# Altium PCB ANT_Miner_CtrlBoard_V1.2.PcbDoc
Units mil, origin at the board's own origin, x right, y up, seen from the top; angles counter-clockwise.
Board outline 5078.74 x 1377.95 mil, 2 copper layers (Top Layer, Bottom Layer); 116 components, 89 nets, 414 pads, 100 vias.
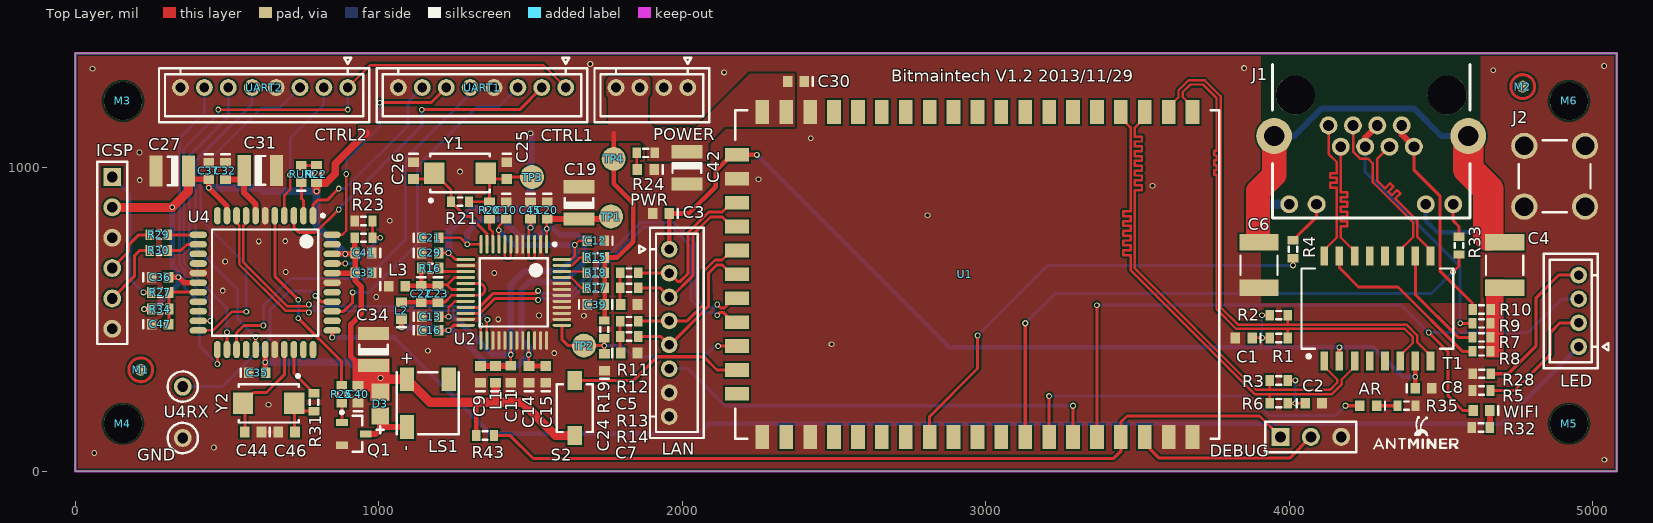
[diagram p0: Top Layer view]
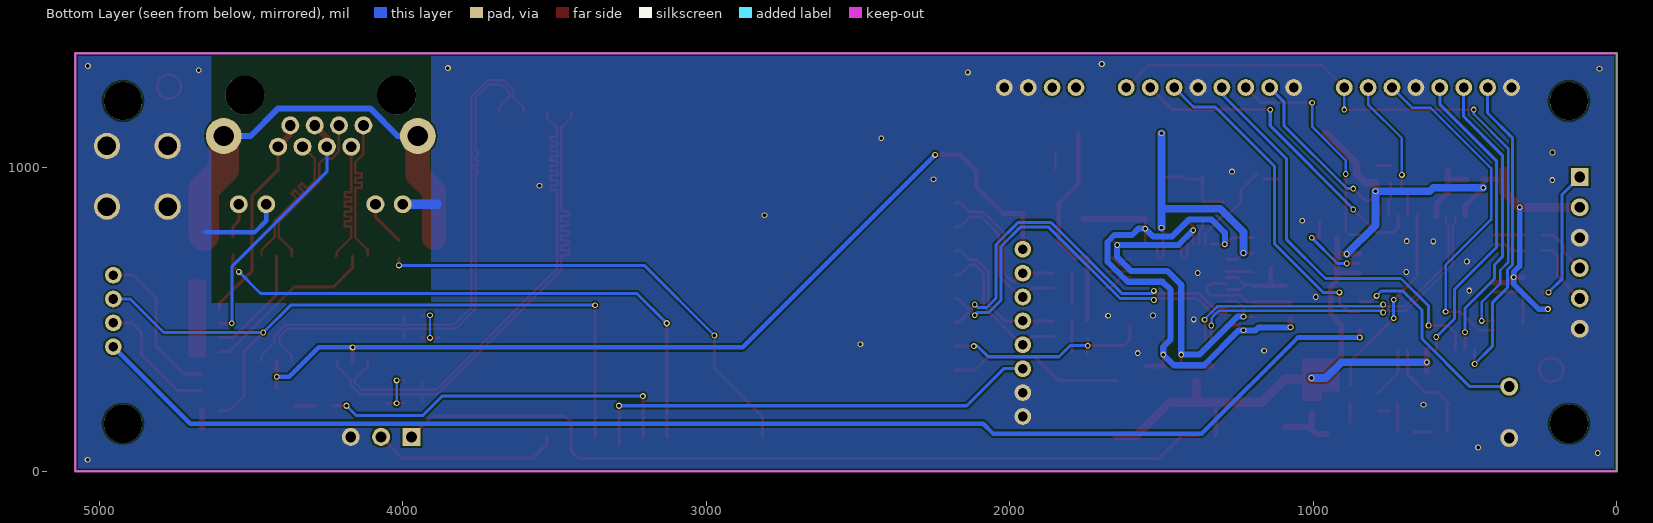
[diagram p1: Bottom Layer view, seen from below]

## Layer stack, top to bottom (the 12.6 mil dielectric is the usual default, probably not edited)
Top Layer: signal copper 1.4
Dielectric: core 12.6, FR-4, Dk 4.8
Bottom Layer: signal copper 1.4

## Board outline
5078.74,1377.95 5078.74,0 0,0 0,1377.95

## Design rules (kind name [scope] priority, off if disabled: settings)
Clearance [All] p1: gap=6
DiffPairsRouting [All] p1: maxlimit=6 minlimit=6 mostfreqgap=6 maxuncoupledlength=500
HoleSize [All] p1: absolutevalues=TRUE maxlimit=200 minlimit=1 maxpercent=80.000 minpercent=20.000
MinimumSolderMaskSliver [All] p1: minsoldermaskwidth=1
PolygonConnect [All] p1: connectstyle=Direct reliefconductorwidth=10 reliefentries=4 polygonreliefangle="90 Angle" airgapwidth=10
RoutingVias [All] p1: holewidth=12 width=20 viastyle="Through Hole" minholewidth=12 minwidth=20 maxholewidth=28 maxwidth=50
SilkToSilkClearance [All] p1: silktosilkclearance=1
SilkToSolderMaskClearance SilkscreenOverComponentPads [IsPad] p1: minsilkscreentomaskgap=1 clearancetoexposedcopper=TRUE
SolderMaskExpansion [All] p1: expansion=4
Width Width_VDD [InNet('VDD')] p1: maxlimit=100 minlimit=10 preferedwidth=10
Width Width_GND [InNet('GND')] p2: maxlimit=100 minlimit=8 preferedwidth=15
Width Width_PLL [InNet('VPLL')] p3: maxlimit=50 minlimit=10 preferedwidth=10
Width Width_VCC [InNet('VCC')] p4: maxlimit=50 minlimit=10 preferedwidth=10
Width [All] p5: maxlimit=100 minlimit=8 preferedwidth=8
23 further rules are at their usual default settings.

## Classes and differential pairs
differential pair D1: +D1_P -D1_N
differential pair LAN1_RX: +LAN1_RX_P -LAN1_RX_N
differential pair LAN1_TX: +LAN1_TX_P -LAN1_TX_N
differential pair USB: +USB_P -USB_N
differential pair WAN_RX: +WAN_RX_P -WAN_RX_N
differential pair WAN_TX: +WAN_TX_P -WAN_TX_N
differential pair WANRX: +WANRX_P -WANRX_N
differential pair WANTX: +WANTX_P -WANTX_N

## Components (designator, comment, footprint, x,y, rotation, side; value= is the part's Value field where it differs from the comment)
AR "Green" LED0603(1608) 4259.84,216.54 r180 top
C1 "100nF" CC0603(1608) 3849.92,439.92 r180 top
C2 "100nF" CC0603(1608) 4079.92,224.92 r0 top
C3 "100nF" CC0603(1608) 1929.92,849.92 r180 top
C4 "10nF/2KV" 1812 4708.92,679.92 r270 top
C5 "100nF" CC0603(1608) 1824.92,549.92 r0 top
C6 "10nF/2KV" 1812 3899.92,679.92 r270 top
C7 "100nF" CC0603(1608) 1824.92,389.92 r0 top
C8 "100nF" CC0603(1608) 4441.92,273.92 r0 top
C9 "4.7uF" CC0603(1608) 1334.92,319.92 r90 top
C10 "100nF" CC0603(1608) 1419.92,859.92 r270 top
C11 "100nF" CC0603(1608) 1435.08,320.08 r90 top
C12 "100nF" CC0603(1608) 1714.92,759.92 r180 top
C13 "100nF" CC0603(1608) 1169.92,509.92 r0 top
C14 "4.7uF" CC0603(1608) 1494.92,319.92 r90 top
C15 "100nF" CC0603(1608) 1549.92,319.92 r90 top
C16 "100nF" CC0603(1608) 1169.92,464.92 r0 top
C19 "22uF/10V" CC1210(3225) 1659.92,884.92 r270 top
C20 "4.7uF" CC0603(1608) 1554.92,859.92 r270 top
C21 "100nF" CC0603(1608) 1169.92,769.92 r0 top
C22 "100nF" CC0603(1608) 1139.92,584.92 r270 top
C23 "100nF" CC0603(1608) 1194.92,584.92 r270 top
C24 "4.7uF" CC0603(1608) 1743.92,359.92 r90 top
C25 "22pF" CC0603(1608) 1421.34,990.98 r270 top
C26 "22pF" CC0603(1608) 1114.25,990.98 r270 top
C27 "22uF/10V" CC1210(3225) 319.92,989.92 r0 top
C29 "100nF" CC0603(1608) 1169.92,719.92 r0 top
C30 "100nF" CC0603(1608) 2374.92,1284.92 r180 top
C31 "10uF/10V" CC1210(3225) 609.88,991.93 r180 top
C32 "100nF" CC0603(1608) 494.92,989.92 r270 top
C33 "100nF" CC0603(1608) 949.92,654.92 r180 top
C34 "22uF/10V" CC1210(3225) 982.92,401.92 r270 top
C35 "100nF" CC0603(1608) 599.92,324.92 r0 top
C36 "100nF" CC0603(1608) 279.92,639.92 r0 top
C37 "100nF" CC0603(1608) 439.92,989.92 r270 top
C39 "100nF" CC0603(1608) 1714.92,549.92 r0 top
C40 "100nF" CC0603(1608) 931.92,253.92 r90 top
C41 "100nF" CC0603(1608) 949.92,719.92 r180 top
C42 "22uF/6.3V" CC1210(3225) 2014.92,999.92 r90 top
C44 "22pF" CC0603(1608) 586.26,129.72 r180 top
C45 "100nF" CC0603(1608) 1499.92,859.92 r270 top
C46 "22pF" CC0603(1608) 696.5,129.72 r0 top
C47 "100nF" CC0603(1608) 279.92,484.92 r0 top
D3 "1N4148" DIODE0805 1004.92,182.92 r180 top
DEBUG "HDR1X3" HDR1X3 3970.92,113.92 r0 top
GND "GND" TP_DIP_1.5mm 354.33,110.24 r0 top
ICSP "HDR1X6" HDR1X6 122.05,970.08 r270 top
J1 "WAN" RJ45_2LED_DIP 4269.69,1240.16 r180 top locked
J2 "SMA HOLE" SMA_HOLE 4874.02,972.44 r0 top
L1 "600/100M" INDC1608L 1384.92,319.92 r90 top
L2 "600/100M" INDC1608L 1074.92,529.92 r90 top
L3 "600/100M" INDC1608L 1059.92,609.92 r0 top
LAN "Header 8" 8PIN_180 1956.69,456.69 r270 top locked
LED "Header 4" 4PIN_180 4952.92,528.81 r90 top
LS1 "Bell" YR5025A 1161.92,224.92 r270 top
M1 "MASK" MASK 215.92,334.92 r0 top
M2 "MASK" MASK 4768.92,1267.92 r0 top
M3 "Mount Hole" HOLE_3.2#1 157.48,1220.47 r0 top locked
M4 "Mount Hole" HOLE_3.2#1 157.48,157.48 r0 top locked
M5 "Mount Hole" HOLE_3.2#2 4763.78,157.48 r0 top locked
M6 "Mount Hole" HOLE_3.2#2 4763.78,1220.47 r0 top locked
POWER "Header 4" 4PIN_180 1899.81,1264.92 r180 top locked
PWR "Red" LED0603(1608) 1879.92,994.92 r180 top
Q1 "MMBT3904" SOT23_L 917.92,123.92 r0 top
R1 "49.9ohm/1%" RR0603(1608) 3964.92,439.92 r0 top
R2 "49.9ohm/1%" RR0603(1608) 3964.92,514.92 r0 top
R3 "49.9ohm/1%" RR0603(1608) 3964.92,299.92 r180 top
R4 "270" RR0603(1608) 4011.92,731.92 r90 top
R5 "NC" RR0603(1608) 4632.92,266.92 r180 top
R6 "49.9ohm/1%" RR0603(1608) 3964.92,224.92 r180 top
R7 "75ohm/1%" RR0603(1608) 4632.92,441.92 r0 top
R8 "75ohm/1%" RR0603(1608) 4632.92,395.92 r0 top
R9 "75ohm/1%" RR0603(1608) 4632.92,487.92 r0 top
R10 "75ohm/1%" RR0603(1608) 4633.39,533.92 r0 top
R11 "49.9ohm/1%" RR0603(1608) 1824.92,654.92 r0 top
R12 "49.9ohm/1%" RR0603(1608) 1824.92,604.92 r0 top
R13 "49.9ohm/1%" RR0603(1608) 1824.92,494.92 r0 top
R14 "49.9ohm/1%" RR0603(1608) 1824.92,444.92 r0 top
R15 "10K" RR0603(1608) 1714.92,704.92 r180 top
R16 "2.43K/1%" RR0603(1608) 1169.92,669.92 r0 top
R17 "510" RR0603(1608) 1714.92,604.92 r0 top
R18 "10K" RR0603(1608) 1714.92,654.92 r0 top
R19 "10K" RR0603(1608) 1742.92,467.92 r90 top
R20 "0" RR0603(1608) 1364.92,859.92 r90 top
R21 "1M" RR0603(1608) 1267.8,888.62 r0 top
R22 "1K" RR0603(1608) 794.92,979.92 r270 top
R23 "0" RR0603(1608) 949.92,769.92 r180 top
R24 "1K" RR0603(1608) 1879.92,1049.92 r0 top
R25 "1K" RR0603(1608) 877.92,253.92 r90 top
R26 "NC" RR0603(1608) 949.92,824.92 r0 top
R27 "10" RR0603(1608) 279.92,589.92 r180 top
R28 "NC" RR0603(1608) 4633.92,321.92 r180 top
R29 "10" RR0603(1608) 275.59,779.53 r180 top
R30 "10" RR0603(1608) 275.59,728.35 r180 top
R31 "0" RR0603(1608) 787.05,228.15 r90 top
R32 "1K" RR0603(1608) 4630.95,144.89 r0 top
R33 "270" RR0603(1608) 4559.06,744.09 r90 top
R34 "4.7K" RR0603(1608) 279.92,534.92 r180 top
R35 "1K" RR0603(1608) 4385.83,216.54 r180 top
R43 "4.7K" RR0603(1608) 1350.39,118.11 r180 top
RUN "Green" LED0603(1608) 744.92,979.92 r90 top
S2 "SW-PB" SWITCH_3x4 1645.67,208.66 r0 top
T1 "PM44-11BP" PM44-11BP 4289.92,536.69 r0 top locked
TP1 "TP" TP2 1764.92,839.92 r180 top
TP2 "TP" TP2 1675.92,414.44 r180 top
TP3 "TP" TP2 1504.92,969.92 r270 top
TP4 "TP" TP2 1773.92,1029.92 r0 top
U1 "AR9331_49PIN" AR9331_49PIN 2263.78,107.95 r0 top locked
U2 "μPD720114" TQFP48_L 1444.92,589.92 r270 top locked
U4 "PIC32MX250F128D" TQFP44_L 625.98,622.05 r270 top locked
U4RX "RX" TP_DIP_1.5mm 354.33,279.53 r0 top
UART1 "CTRL1" 8PIN_180 1340.33,1264.92 r180 top locked
UART2 "CTRL2" 8PIN_180 622.51,1264.92 r180 top locked
WIFI "Green" LED0603(1608) 4632.92,200.92 r180 top
Y1 "30MHz" 4SMX 1267.8,983.11 r0 top
Y2 "8M" 4SMX 637.44,224.21 r180 top

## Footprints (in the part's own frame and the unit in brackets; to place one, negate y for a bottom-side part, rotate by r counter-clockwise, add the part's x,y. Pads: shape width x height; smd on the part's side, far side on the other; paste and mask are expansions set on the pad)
4PIN_180 [mm]
  round 1.4 hole 0.8: 1(-3,0) 2(-1,0) 3(1,0) 4(3,0)
  silkscreen extent -4.8,-2.5 4.8,2.9, body extent -5,-1.8 5,3, height 6.1
4SMX [mm]
  rect 1.7x1.8 smd: 1(-2.15,0) 2(2.15,0)
  silkscreen extent -2.57,-2.42 2.5,1.6
8PIN_180 [mm]
  round 1.4 hole 0.8: 1(-7,0) 2(-5,0) 3(-3,0) 4(-1,0) 5(1,0) 6(3,0) 7(5,0) 8(7,0)
  silkscreen extent -8.8,-2.5 8.8,2.9, body extent -9,-1.8 9,3, height 6.1
1812 [mm] "Chip Capacitor, Body 4.5x3.2mm, IPC High Density"
  rect 1.4x3.3 smd: 1(-1.9,0) 2(1.9,0)
  silkscreen extent -0.8,-1.55 0.8,1.55, body extent -2.4,-1.7 2.4,1.7, height 1.4
AR9331_49PIN [mm] "AR9331 49PIN"
  rect 1.143x2 smd: 1(0,0.158) 2(2,0.158) 3(4,0.158) 4(6,0.158) 5(8,0.158) 6(10,0.158) 7(12,0.158) 8(14,0.158) 9(16,0.158) 10(18,0.158) 11(20,0.158) 12(22,0.158) 13(24,0.158) 14(26,0.158) 15(28,0.158) 16(30,0.158) 17(32,0.158) 18(34,0.158) 19(36,0.158) 20(36,27.341) 21(34,27.341) 22(32,27.341) 23(30,27.341) 24(28,27.341) 25(26,27.341) 26(24,27.341) 27(22,27.341) 28(20,27.341) 29(18,27.341) 30(16,27.341) 31(14,27.341) 32(12,27.341) 33(10,27.341) 34(8,27.341) 35(6,27.341) 36(4,27.341) 37(2,27.341) 38(0,27.341)
  rect 2x1.146 smd: 39(-2.11,23.75) 40(-2.11,21.75) 41(-2.11,19.75) 42(-2.11,17.75) 43(-2.11,15.75) 44(-2.11,13.75) 45(-2.11,11.75) 46(-2.11,9.75) 47(-2.11,7.75) 48(-2.11,5.75) 49(-2.11,3.75)
  silkscreen extent -2.25,0 38.25,27.5
CC0603(1608) [mm] "Chip Capacitor, Body 1.6x0.8mm, IPC High Density"
  rect 0.8x0.9 smd: 1(-0.7,0) 2(0.7,0)
  silkscreen extent -1.4,-0.35 -1.4,0.35, body extent -0.87,-0.48 0.87,0.47, height 0.85
CC1210(3225) [mm] "Chip Capacitor, Body 3.2x2.5mm, IPC High Density"
  rect 1.1x2.6 smd: 1(-1.35,0) 2(1.35,0)
  silkscreen extent -0.4,-1.2 0.42,1.2, body extent -1.7,-1.35 1.7,1.35, height 1.35
DIODE0805 [mm]
  rect 1.5x1.4 smd: 1(0,0) 2(0,-2)
  silkscreen extent -0.28,0.88 0.28,1.44, body extent -0.7,-2.07 0.7,0.07, height 0.7
HDR1X3 [mm] "Connector; Header; 3 Position"
  rect 1.5x1.5 hole 0.9: 1(0,0)
  round 1.5 hole 0.9: 2(2.54,0) 3(5.08,0)
  silkscreen extent -1.27,-1.27 6.35,1.27
HDR1X6 [mm] "Connector; Header; 6 Position"
  rect 1.5x1.5 hole 0.9: 1(0,0)
  round 1.5 hole 0.9: 2(2.54,0) 3(5.08,0) 4(7.62,0) 5(10.16,0) 6(12.7,0)
  silkscreen extent -1.27,-1.27 13.97,1.27
HOLE_3.2#1 [mm]
  round 3.2 hole 3.2 unplated: 0(0,0)
HOLE_3.2#2 [mm]
  round 3.2 hole 3.2 unplated: 0(4,0)
INDC1608L [mm] "Chip Inductor, Body 1.6x0.8mm, IPC High Density"
  rect 0.8x0.9 smd: 1(-0.7,0) 2(0.7,0)
  silkscreen extent -1.4,-0.35 -1.4,0.35, body extent -0.87,-0.48 0.87,0.48, height 0.55
LED0603(1608) [mm] "Chip LED, Body 1.6x0.8mm, IPC High Density"
  rect 0.8x0.9 smd: 1(0.7,0) 2(-0.7,0)
  silkscreen extent -1.4,-0.35 -1.4,0.35, body extent -0.87,-0.48 0.87,0.47, height 0.85
MASK [mm] "SMD MASK 1mm"
  round 1 smd: 0(0,0)
  Top Layer circle w0.254: c0,0 r1
PM44-11BP [mm]
  rect 0.64x1.6 smd: 1(-4.445,-4.4) 2(-3.175,-4.4) 3(-1.905,-4.4) 4(-0.635,-4.4) 5(0.635,-4.4) 6(1.905,-4.4) 7(3.175,-4.4) 8(4.445,-4.4) 9(4.445,4.4) 10(3.175,4.4) 11(1.905,4.4) 12(0.635,4.4) 13(-0.635,4.4) 14(-1.905,4.4) 15(-3.175,4.4) 16(-4.445,4.4)
  silkscreen extent -6.35,-4.15 6.35,3.35
RJ45_2LED_DIP [mm]
  round 1.5 hole 0.9: 1(3.57,2.54) 2(2.55,4.32) 3(1.53,2.54) 4(0.51,4.32) 5(-0.51,2.54) 6(-1.53,4.32) 7(-2.55,2.54) 8(-3.57,4.32) 9(6.86,9.14) 10(4.57,9.14) 11(-4.57,9.14) 12(-6.86,9.14)
  round 3 hole 1.7: 13(8.125,3.43) 14(-8.125,3.43)
  round 3.25 hole 3.25: ""(-6.35,0) ""(6.35,0)
  silkscreen extent -8.26,-2.54 8.26,10.29
RR0603(1608) [mm] "Chip Resistor, Body 1.6x0.8mm, IPC High Density"
  rect 0.7x0.9 smd: 1(-0.75,0) 2(0.75,0)
  silkscreen extent -0.2,-0.35 0.2,0.35, body extent -0.85,-0.48 0.85,0.47, height 0.6
SMA_HOLE [mm] "SMA Socket Assembly Hole."
  round 2.2 hole 1.55: 1(-2.54,2.54) 2(2.54,2.54) 3(-2.54,-2.54) 4(2.54,-2.54)
  silkscreen extent -3,-3 3,3
SOT23_L [mm] "SOT23, 3-Leads, Body 2.9x1.3mm, Pitch 0.95mm, Lead Span 2.3mm - Reverse Pinning, IPC High Density"
  rect 1x0.6 smd: 1(-1,0.95) 2(-1,-0.95) 3(1,0)
  silkscreen extent -1.12,-1.5 0.7,1.92, body extent -0.7,-1.5 0.7,1.5, height 1.1
SWITCH_3x4 [mm]
  rect 1.2x1.6 smd: 1(0,2.3) 2(0,-2.3)
  silkscreen extent -1.5,-2 1.5,2
TP2 [mm] "Test Point 2mm SMD"
  round 2 smd: 1(0,0)
TP_DIP_1.5mm [mm]
  round 1.5 hole 0.9: 1(0,0)
  silkscreen extent -1.27,-1.27 1.27,1.27
TQFP44_L [mm] "Thin QFP, 44-Leads, Body 10x10mm, Pitch 0.8mm, IPC High Density"
  oval 1.45x0.55 smd: 1(-5.6,4) 2(-5.6,3.2) 3(-5.6,2.4) 4(-5.6,1.6) 5(-5.6,0.8) 6(-5.6,0) 7(-5.6,-0.8) 8(-5.6,-1.6) 9(-5.6,-2.4) 10(-5.6,-3.2) 11(-5.6,-4) 23(5.6,-4) 24(5.6,-3.2) 25(5.6,-2.4) 26(5.6,-1.6) 27(5.6,-0.8) 28(5.6,0) 29(5.6,0.8) 30(5.6,1.6) 31(5.6,2.4) 32(5.6,3.2) 33(5.6,4)
  oval 0.55x1.45 smd: 12(-4,-5.6) 13(-3.2,-5.6) 14(-2.4,-5.6) 15(-1.6,-5.6) 16(-0.8,-5.6) 17(0,-5.6) 18(0.8,-5.6) 19(1.6,-5.6) 20(2.4,-5.6) 21(3.2,-5.6) 22(4,-5.6) 34(4,5.6) 35(3.2,5.6) 36(2.4,5.6) 37(1.6,5.6) 38(0.8,5.6) 39(0,5.6) 40(-0.8,5.6) 41(-1.6,5.6) 42(-2.4,5.6) 43(-3.2,5.6) 44(-4,5.6)
  silkscreen extent -5.72,-4.45 4.45,4.95, body extent -5,-5 5,5, height 1.6
TQFP48_L [mm]
  oval 1.55x0.25 smd: 1(-4.025,2.75) 2(-4.025,2.25) 3(-4.025,1.75) 4(-4.025,1.25) 5(-4.025,0.75) 6(-4.025,0.25) 7(-4.025,-0.25) 8(-4.025,-0.75) 9(-4.025,-1.25) 10(-4.025,-1.75) 11(-4.025,-2.25) 12(-4.025,-2.75) 25(4.025,-2.75) 26(4.025,-2.25) 27(4.025,-1.75) 28(4.025,-1.25) 29(4.025,-0.75) 30(4.025,-0.25) 31(4.025,0.25) 32(4.025,0.75) 33(4.025,1.25) 34(4.025,1.75) 35(4.025,2.25) 36(4.025,2.75)
  oval 0.25x1.55 smd: 13(-2.75,-4.025) 14(-2.25,-4.025) 15(-1.75,-4.025) 16(-1.25,-4.025) 17(-0.75,-4.025) 18(-0.25,-4.025) 19(0.25,-4.025) 20(0.75,-4.025) 21(1.25,-4.025) 22(1.75,-4.025) 23(2.25,-4.025) 24(2.75,-4.025) 37(2.75,4.025) 38(2.25,4.025) 39(1.75,4.025) 40(1.25,4.025) 41(0.75,4.025) 42(0.25,4.025) 43(-0.25,4.025) 44(-0.75,4.025) 45(-1.25,4.025) 46(-1.75,4.025) 47(-2.25,4.025) 48(-2.75,4.025)
  silkscreen extent -4.15,-2.85 2.85,3.55, body extent -3.5,-3.5 3.5,3.5, height 1.6
YR5025A [mm]
  rect 2x1.2 smd: 1(-2,-1.75) 2(2,-1.75) ""(-2,1.75)
  silkscreen extent -2.6,-2.6 2.6,2.6

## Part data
AR PWR RUN WIFI: library part LED0, "Typical INFRARED GaAs LED"
C1 C2 C3 C4 C5 C6 C7 C8 C9 C10 C11 C12 C13 C14 C15 C16 C19 C20 C21 C22 C23 C24 C25 C26 C27 C29 C30 C31 C32 C33 C34 C35 C36 C37 C39 C40 C41 C42 C44 C45 C46 C47: library part "Cap Semi", "Capacitor (Semiconductor SIM Model)"
D3: library part "Diode 1N4148", "High Conductance Fast Diode"
DEBUG: library part "Header 3", "Header, 3-Pin"
GND U4RX: library part TP
ICSP: library part "Header 6", "Header, 6-Pin"
J1: library part RJ45-DIP, "RJ45,DUAL LED,DIP"
J2: library part SMA_HOLE, "SMA Socket Assembly Hole."
L1 L2 L3: library part Inductor, "Inductor"
LAN: "Header, 8-Pin"
LED POWER: "Header, 4-Pin"
LS1: "Electrical Bell"
M3 M4 M5 M6: library part M_Hole
Q1: "NPN Switching Transistor"
R1 R2 R3 R4 R5 R6 R7 R8 R9 R10 R11 R12 R13 R14 R15 R16 R17 R18 R19 R20 R21 R22 R23 R24 R25 R26 R27 R28 R29 R30 R31 R32 R33 R34 R35 R43: library part Res1, "Resistor"
S2: "Switch"
TP1 TP2 TP3 TP4: library part TP2
U2: library part uPD720114
UART1 UART2: library part "Header 8", "Header, 8-Pin"
Y1 Y2: library part XTAL, "Crystal Oscillator"

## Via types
v1: diameter 19, hole 12, Top Layer to Bottom Layer, 87 vias
v2: diameter 20, hole 12, Top Layer to Bottom Layer, 13 vias

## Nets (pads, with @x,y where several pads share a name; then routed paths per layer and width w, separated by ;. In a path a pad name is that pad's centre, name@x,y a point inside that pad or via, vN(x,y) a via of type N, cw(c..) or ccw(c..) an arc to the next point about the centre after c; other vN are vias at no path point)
AR9331_LED: AR.1 U1.13 | length 1196.6
  Top Layer w10: U1.13 v2(3208.66,248.03) ; v2(4185.04,216.54) AR.1
  Bottom Layer w10: v2(3208.66,248.03) 3870.08,248.03 3933.07,185.04 4153.54,185.04 v2(4185.04,216.54)
AR9331_RX: DEBUG.1 R43.1 U1.16 | length 2764.6
  Top Layer w10: R43.1 1433.07,118.11 1507.87,43.31 3421.26,43.31 3444.89,66.94 U1.16 3444.89,162.89 3464.92,182.92 3901.92,182.92 DEBUG.1
AR9331_TX: DEBUG.2 U1.17 | length 618.8
  Top Layer w10: U1.17 3523.63,91.21 3570.92,43.92 4000.92,43.92 DEBUG.2
BEEP: R25.2 U4.5 | length 650.4
  Top Layer w10: U4.5 657.48,643.36 v1(734.92,565.92) ; v1(734.92,504.92) 877.92,361.92 R25.2
  Bottom Layer w10: v1(734.92,504.92) v1(734.92,565.92)
D1_N: U2.25 U4.9 | length 1110.7
  Top Layer w8: U4.9 531.5,819.35 540.24,810.6 540.24,682.6 692.92,529.92 763.92,529.92 v2(769.92,523.92) ; v1@1334.92,479.92 1336.65,478.19 U2.25
  Bottom Layer w8: v2@769.92,524.92 774.92,529.92 1310.12,529.92 1334.92,505.12 v1@1334.92,479.92
  other v1: 1335.92,480.92
D1_P: U2.26 U4.8 | length 1115.7
  Top Layer w8: U4.8 562.99,818.99 554.24,810.24 554.24,688.6 698.92,543.92 763.92,543.92 v2(769.92,549.92) ; U2.26 v1@1356.34,497.92
  Bottom Layer w8: v2(769.92,549.92) 775.92,543.92 1315.92,543.92 1354.92,504.92 v1@1354.92,494.92
  other v1: 1357.92,499.92
FAN1_SPEED: U4.3 UART1.2 | length 1093
  Top Layer w10: U4.3 720.47,803.37 736.92,786.92 791.92,786.92 v1(867.92,862.92) ; v1(1141.73,1191.92) 1464.18,1191.92 UART1.2
  Bottom Layer w10: v1(867.92,862.92) 867.92,864.92 1141.73,1138.73 v1(1141.73,1191.92)
FAN2_SPEED: U4.4 UART2.2 | length 476.4
  Top Layer w8: U4.4 688.98,908.98 707.92,927.92 v1(707.92,976.92)
  Bottom Layer w8: v1(707.92,976.92) 707.92,1097.92 819.36,1209.36 UART2.2
FAN_PWM: U4.21 UART1.1 UART2.1 | length 2097.3
  Top Layer w8: U4.21 v1(444.96,496.06) ; v1(471.1,1192.1) v1(898.1,1192.1) ; UART2.1 972.1,1338.92 1541.92,1338.92 UART1.1
  Bottom Layer w8: v1(444.96,496.06) 444.96,558.04 384,619 384,662.84 358,688.84 358,1064 471.1,1177.1 v1(471.1,1192.1) ; v1(898.1,1192.1) UART2.1
GND: C1.2 C2.2 C3.2 C5.2 C6.2 C7.2 C8.2 C9.1 C10.1 C11.1 C12.1 C13.1 C14.1 C15.1 C16.1 C19.1 C20.1 C21.1 C24.1 C25.1 C26.1 C27.1 C29.1 C30.1 C31.1 C32.1 C33.1 C34.1 C35.1 C36.1 C37.1 C39.1 C40.1 C41.1 C42.1 C44.1 C45.1 C46.1 C47.1 DEBUG.3 GND.1 ICSP.3 ICSP.6 J1.9 J1.11 J2.1 J2.2 J2.3 J2.4 L3.1 LAN.7 LAN.8 POWER.1 POWER.2 PWR.2 Q1.2 R5.2 R26.1 R28.2 R32.1 R35.1 U1.1 U1.3 U1.18 U1.19 U1.36 U1.40 U2.2 U2.5 U2.6 U2.14 U2.23 U2.27 U2.28 U2.29 U2.31 U2.32 U2.34 U2.35 U2.36 U2.38 U2.39 U2.40 U2.41 U2.42 U2.43 U2.44 U4.6 U4.16 U4.29 U4.39 UART1.4 UART1.8 UART2.4 UART2.8 | length 438.5
  Top Layer w9: C44.1 C46.1
  Bottom Layer w15: J1.11 4449.61,825.98 4488.19,787.4 4649.61,787.4
  Bottom Layer w30: 3886.53,880.32 J1.9
  other v1: 5037.92,38.92 62.92,60.92 636.92,219.92 1577.92,389.92 1161.92,397.92 2491.92,418.92 1393.92,500.92 1675.92,512.92 1527.92,513.92 991.92,574.92 485.92,595.92 1380.92,653.92 693.92,656.92 493.92,691.92 604.92,757.92 691.92,758.92 1035.92,825.92 2807.92,843.92 3548.92,940.92 212.92,959.92 2250.92,962.92 1267.92,987.92 211.92,1050.92 2422.92,1097.92 4671.92,1321.92 56.92,1326.92 3850.92,1328.92 5036.92,1335.92
  other v2: 456.69,78.74 2137.8,1314.96 1696.85,1342.52
HUB_CLK: C25.2 R20.2 R21.2 TP3.1 Y1.2 | length 274.3
  Top Layer w9: R21.2 R20.2@1364.09,888.62 ; R20.2 Y1.2@1364.92,970.63 ; Y1.2@1372.13,963.43 C25.2 ; C25.2@1427.83,969.92 TP3.1
HUB_RST: C24.2 R19.1 TP2.1 U1.47 U2.37 | length 709.6
  Top Layer w10: U2.37 1603.39,435.46 1624.41,414.44 v1(1742.92,414.44) ; C24.2@1742.92,390.48 R19.1 ; v1(2118.07,413.07) U1.47
  Bottom Layer w10: v1(1742.92,414.44) 1801.41,414.44 1837.92,377.92 2070.92,377.92 2105.92,412.92 v1@2117.92,412.92
LAN1_LED: LAN.6 U1.14 | length 1508.4
  Top Layer w10: U1.14@3287.4,89.4 U1.14 v2(3287.4,216.54)
  Bottom Layer w10: LAN.6 2019.69,338.58 2141.73,216.54 v2(3287.4,216.54)
LAN1_RX_N: LAN.3 R12.2 U1.42 | length 539.9
  Top Layer w10: R12.2 1926.57,604.92 LAN.3 1964.8,574.8 2034.92,644.92 2034.92,779.92 2093.14,838.14 2131.7,838.14 2163.07,806.77 U1.42
LAN1_RX_P: LAN.2 R11.2 U1.41 | length 522.7
  Top Layer w10: R11.2@1855.83,653.54 LAN.2 1984,626.24 1993.61,626.24 2018.92,651.55 2018.92,786.55 2086.52,854.14 2131.14,854.14 2162.51,885.51 U1.41
LAN1_TX_N: LAN.5 R14.2 U1.44 | length 523.6
  Top Layer w10: R14.2 1929.09,444.92 LAN.5 1959.95,417.32 2085.92,543.29 2085.92,652.29 2114.29,680.66 2131.18,680.66 2162.55,649.29 U1.44
LAN1_TX_P: LAN.4 R13.2 U1.43 | length 485.1
  Top Layer w10: R13.2@1855.59,496.06 LAN.4 2016.06,496.06 2069.92,549.92 2069.92,658.92 2107.66,696.66 2130.66,696.66 2162.03,728.03 U1.43
LED: RUN.2 U4.2 | length 112.8
  Top Layer w10: RUN.2 744.92,899.92 751.97,892.87 U4.2
LED2: LED.1 U4.34 | length 4379.1
  Top Layer w15: v1(846.46,441.39) U4.34
  Bottom Layer w15: v1(846.46,441.39) 1050.46,441.39 1366.92,124.92 2054.92,124.92 2087.48,157.48 4699.7,157.48 LED.1
NET_POW: C3.1 C8.1 LAN.1 T1.2 T1.7 U1.39 | length 3119.9
  Top Layer w15: LAN.1 C3.1@1956.69,849.13 ; C3.1 2021.92,849.92 2109.92,937.92 2109.92,989.92 2162.99,1042.99 U1.39 v1(2245.85,1042.99) ; T1.2 v2(4164.92,408.92) ; C8.1@4414.92,276.48 v1(4414.92,311.92) T1.7
  Bottom Layer w15: v1@2245.92,1042.92 2879.92,408.92 v2(4164.92,408.92) 4276.92,408.92 4373.92,311.92 v1(4414.92,311.92)
NetAR_2: AR.2 R35.2 | length 68.9
  Top Layer w10: AR.2 R35.2
NetC1_1: C1.1 R1.1 R2.1 | length 159.8
  Top Layer w8: C1.1 3906.44,439.92 R1.1 ; v1(3909.92,514.92) R2.1
  Bottom Layer w8: v1@3906.44,511.44 v1(3909.92,514.92) ; v1(3909.92,439.92) v1@3909.92,511.44
NetC2_1: C2.1 R3.1 R6.1 | length 158.4
  Top Layer w8: R6.1 C2.1 ; R3.1 v1(4019.92,299.92)
  Bottom Layer w8: v1(4019.92,224.92) v1(4019.92,299.92)
NetC4_1: C4.1 C6.1 J1.13 J1.14 | length 1427.4
  Top Layer w80: C6.1@3896.92,769.92 3896.92,923.92 3949.8,976.8 J1.13
  Top Layer w100: J1.14 4589.57,995.28 4654.92,929.92 C4.1@4654.92,776.92
  Bottom Layer w20: J1.13 4016.12,1105.12 4106.92,1195.92 4409.92,1195.92 4500.72,1105.12 J1.14
NetC4_2: C4.2 R7.2 R8.2 R9.2 R10.2
NetC5_1: C5.1 R11.1 R12.1 | length 108
  Top Layer w10: C5.1@1795.39,551.89 R12.1 ; R12.1@1795.39,599.92 R11.1
NetC7_1: C7.1 R13.1 R14.1 | length 103
  Top Layer w10: C7.1@1795.39,391.89 R14.1 R13.1
NetC22_1: C22.1 C23.1 L3.2 R16.1 U2.16 U2.18 | length 328.8
  Top Layer w9: C23.1@1197.36,614.92 1224.92,614.92 ; U2.18 1240.08,599.76 1224.92,614.92 ; U2.16 1249.13,639.13 1224.92,614.92
  Top Layer w15: L3.2@1090.04,612.48 C22.1 ; R16.1@1139.92,669.45 C22.1 ; C23.1 C22.1
NetC22_2: C22.2 C23.2 L2.2 U2.17 U2.19 | length 370.3
  Top Layer w9: C23.2 1217.36,557.36 1240.08,580.08 U2.19 1330.08,580.08 ccw(c1330.08,599.92) 1349.92,599.92 ccw(c1330.39,599.92) 1330.39,619.45 U2.17
  Top Layer w15: L2.2@1074.92,557.36 C22.2 C23.2
NetC26_2: C26.2 R21.1 U2.11 Y1.1 | length 363.3
  Top Layer w10: C26.2 Y1.1@1163.46,963.43 ; Y1.1 1238.27,927.99 R21.1 1286.97,839.92 1299.92,839.92 1356.34,783.5 U2.11
NetC44_2: C44.2 U4.30 Y2.2 | length 346.6
  Top Layer w10: Y2.2 588.5,259.92 629.92,259.92 688.98,318.98 U4.30 ; C44.2 Y2.2@558.7,218.31
NetC46_2: C46.2 R31.1 Y2.1 | length 131.9
  Top Layer w10: C46.2@722.09,131.69 Y2.1 ; Y2.1@747.68,198.62 R31.1
NetD3_1: D3.1 LS1.2 Q1.3 | length 193.9
  Top Layer w20: Q1.3 989.92,123.92 1004.92,138.92 D3.1@1004.92,190.92 ; 1004.92,146.18 LS1.2
NetICSP_1: ICSP.1 R27.2 | length 448.2
  Top Layer w10: v1(224.92,589.92) R27.2
  Bottom Layer w10: ICSP.1 179.92,912.2 179.92,634.92 v1(224.92,589.92)
NetICSP_4: ICSP.4 R29.2 | length 182.2
  Top Layer w10: ICSP.4 174.92,722.95 174.92,744.92 209.53,779.53 R29.2
NetICSP_5: ICSP.5 R30.2 | length 228.8
  Top Layer w10: ICSP.5 194.92,642.95 194.92,709.92 213.35,728.35 R30.2
NetJ1_4: J1.4 J1.5 R9.1 | length 839.3
  Top Layer w10: v1(4562.63,487.92) R9.1
  Top Layer w20: J1.4 4249.61,1100 J1.5
  Bottom Layer w10: J1.4 4249.61,987.28 4562.63,674.25 v1(4562.63,487.92)
NetJ1_7: J1.7 J1.8 R10.1 | length 703.1
  Top Layer w10: J1.8 4410.24,993.61 4495.92,907.92 4495.92,661.56 4603.87,553.61 R10.1
  Top Layer w20: J1.7 4370.08,1110.24 J1.8
NetJ1_10: J1.10 R4.2 | length 151.1
  Top Layer w10: R4.2 4089.76,839.29 J1.10
NetJ1_12: J1.12 R33.2 | length 114.7
  Top Layer w10: J1.12 4539.76,826.38 4559.06,807.09 R33.2
NetLED_2: LED.2 R5.1 | length 425.4
  Top Layer w10: R5.1 4741.92,266.92 4860.92,385.92 4860.92,458.92 4891.44,489.44 LED.2
NetLED_4: LED.4 R28.1 | length 516.6
  Top Layer w10: R28.1 4720.92,321.92 4811.92,412.92 4811.92,570.92 4887.92,646.92 LED.4
NetPWR_1: PWR.1 R24.1 | length 53
  Top Layer w8: PWR.1@1850.39,996.89 R24.1
NetQ1_1: Q1.1 R25.1 | length 63.1
  Top Layer w10: Q1.1 R25.1@878.55,224.39
NetR7_1: R7.1 T1.10 | length 373.9
  Top Layer w10: T1.10 4414.92,582.92 4555.92,441.92 R7.1
NetR8_1: R8.1 T1.15 | length 591.4
  Top Layer w10: T1.15 4164.92,670.92 4227.92,607.92 4357.92,607.92 4569.92,395.92 R8.1
NetR15_2: R15.2 U2.47 | length 93
  Top Layer w8: U2.47 1636.97,678.5 1663.39,704.92 R15.2
NetR16_2: R16.2 U2.15 | length 85.9
  Top Layer w9: R16.2@1200.55,658.82 U2.15
NetR17_1: R17.1 U2.45 | length 96.2
  Top Layer w8: U2.45 1634.37,639.13 1668.58,604.92 R17.1
NetR18_1: R18.1 U2.46 | length 76.8
  Top Layer w8: U2.46 R18.1@1680.16,658.82
NetR20_1: R20.1 U2.10 | length 86.6
  Top Layer w9: R20.1 1364.92,799.92 1376.02,788.82 U2.10
NetR22_1: R22.1 RUN.1 | length 48
  Top Layer w10: RUN.1 R22.1@792.95,1007.48
NetR31_2: R31.2 U4.31 | length 171.5
  Top Layer w10: U4.31 720.47,324.25 R31.2
NetR32_2: R32.2 WIFI.2 | length 56
  Top Layer w20: R32.2 WIFI.2
NetS2_1: S2.1 U1.48 | length 585.7
  Top Layer w10: S2.1 1838.58,299.21 1917.32,377.95 2070.87,377.95 2114.49,334.33 U1.48
NetU2_7: U2.7 U2.8 | length 106.9
  Top Layer w8: U2.8 1415.39,709.92 ccw(c1424.39,709.92) 1424.39,700.92 1426.08,700.92 ccw(c1426.08,709.92) 1435.08,709.92 U2.7
PGEC: R30.1 U4.13 | length 108.5
  Top Layer w10: R30.1 348.35,728.35 368.03,748.03 U4.13
PGED: R29.1 U4.12 | length 100.4
  Top Layer w10: R29.1 U4.12
PIC_RESET: C47.2 R27.1 R34.1 U4.18 | length 199.4
  Top Layer w10: C47.2@309.45,486.89 R34.1 R27.1 310.08,590.55 U4.18
TEMP_SCL1: U4.44 UART1.6 | length 759
  Top Layer w8: U4.44 879.53,779.53 892.92,792.92 v1(892.92,979.92)
  Top Layer w10: v1(1003.92,1214.92) 1172.22,1214.92 UART1.6
  Bottom Layer w8: v1(892.92,979.92) 892.92,1024.92 1003.92,1135.92 v1(1003.92,1214.92)
TEMP_SCL2: U4.24 UART2.6 | length 967.1
  Top Layer w10: U4.24 v1(500,459)
  Bottom Layer w10: v1(500,459) 500,538 403,635 403,681 377,707 377,1042 504.4,1169.4 UART2.6
TEMP_SDA1: U4.1 UART1.7 | length 602
  Top Layer w10: U4.1 783.46,878.46 798.92,893.92 829.92,893.92 v1(867.92,931.92)
  Bottom Layer w10: v1(867.92,931.92) 888.92,931.92 1096.92,1139.92 1096.92,1218.36 UART1.7
TEMP_SDA2: U4.23 UART2.7 | length 1044.7
  Top Layer w10: v1(468.5,354) U4.23
  Bottom Layer w10: UART2.7 425.66,1180.66 343,1098 343,682.13 360.42,664.71 360.42,605.58 410,556 410,412.5 v1(468.5,354)
U1RX: U4.36 UART1.3 | length 1086.6
  Top Layer w10: U4.36 884.56,527.56 913.92,556.92 v1(913.92,589.92)
  Bottom Layer w10: v1(913.92,589.92) 967.78,589.92 1127.92,750.06 1127.92,1005.92 1322.92,1200.92 1394.44,1200.92 UART1.3
U1TX: U4.25 UART1.5 | length 1365.5
  Top Layer w10: U4.25 531.5,456.5 555.92,480.92 v2(619.92,480.92)
  Bottom Layer w10: v2(619.92,480.92) 619.92,545.12 710.72,635.92 959.92,635.92 1088.92,764.92 1088.92,1030.92 1300.96,1242.96 UART1.5
U2RX: U4.22 UART2.3 | length 1155.8
  Top Layer w8: U4.22 453.57,464.57 514.92,525.92 v1(563.92,525.92)
  Bottom Layer w8: v1(563.92,525.92) 563.92,679.92 414,829.84 414,999 612.92,1197.92 673.62,1197.92 UART2.3
U2TX: U4.27 UART2.5 | length 1022.4
  Top Layer w10: U4.27 v1@594.49,442.92
  Bottom Layer w10: UART2.5 583.14,1210.14 397,1024 397,737.84 534.92,599.92 534.92,502.92 v1(594.92,442.92)
U3RX: U4.43
U3TX: U4.38
U4RX: U4.37 U4RX.1 | length 692.6
  Top Layer w10: v2(791.34,578.74) 811.02,559.06 U4.37
  Bottom Layer w10: U4RX.1 484.25,279.53 641.73,437.01 641.73,531.5 704.72,594.49 775.59,594.49 v2(791.34,578.74)
U4TX: U4.33
USB_ID: R23.1 R26.2 U4.41 | length 274.1
  Top Layer w10: U4.41 v1(889.8,685.04) ; R26.2 R23.1 v1(1004.92,769.92)
  Bottom Layer w10: v1(889.8,685.04) 920.04,685.04 v1(1004.92,769.92)
USB_N: U1.45 U2.21 | length 1264.9
  Top Layer w10: U2.21 1330.71,540.71 1375.92,585.92 1515.92,585.92 v1(1524.92,594.92) ; v1(2114.92,549.92) 2125.66,539.18 2139.18,539.18 2170.55,570.55 U1.45
  Bottom Layer w8: 1849.92,804.92 1854.02,809.02
  Bottom Layer w10: v1(1524.92,594.92) 1533.92,585.92 1629.51,585.92 1849.51,805.92 1864.51,820.92 1971.55,820.92 2044.92,747.55 2044.92,570.42 2074.92,540.42 2105.42,540.42 v1(2114.92,549.92)
USB_P: U1.46 U2.22 | length 1256.3
  Top Layer w10: U2.22 1333.65,521.02 1382.55,569.92 1519.92,569.92 v1(1524.92,564.92) ; v1(2114.92,514.92) 2123.18,523.18 2136.66,523.18 2168.03,491.81 U1.46
  Bottom Layer w10: v1(1524.92,564.92) 1529.92,569.92 1636.13,569.92 1856.13,789.92 1871.13,804.92 1964.92,804.92 2028.92,740.92 2028.92,563.79 2068.29,524.42 2105.42,524.42 v1(2114.92,514.92)
VCAP: C31.2 C32.2 U4.7 | length 230
  Top Layer w20: C32.2 C31.2@556.73,962.36 ; C31.2 C31.2@556.73,962.36 ; C31.2@559.92,962.36 C31.2@556.73,962.36 ; U4.7 594.49,880.35 556.73,918.11 C31.2@556.73,962.36
VDD2V5_1: C14.2 C15.2 C16.2 C19.2 C20.2 C21.2 L2.1 TP1.1 U2.1 U2.12 U2.24 U2.33 | length 2207.9
  Top Layer w9: C21.2 1269.92,769.92 v1(1291.46,748.39) U2.12 ; C14.2@1494.13,348.27 v1(1494.13,384.92) U2.33 ; U2.1 v1(1553.19,799.92) C20.2@1553.19,830.63
  Top Layer w10: C16.2 v1(1229.92,464.92) 1246.65,481.65 U2.24
  Top Layer w15: C14.2 C15.2
  Top Layer w20: v1(1074.92,474.92) L2.1 ; C20.2 C19.2@1659.33,832.36 ; C19.2 TP1.1@1756.77,831.77
  Bottom Layer w20: v1(1074.92,474.92) 1179.92,474.92 1189.92,464.92 v1(1229.92,464.92) 1244.92,464.92 1359.92,349.92 1459.13,349.92 v1(1494.13,384.92) 1494.13,410.71 1469.92,434.92 1469.92,597.92 1496.92,624.92 1611.92,624.92 1677.92,690.92 1677.92,755.92 1654.92,778.92 1596.92,778.92 1575.92,799.92 v1(1553.19,799.92) 1527.19,773.92 1465.92,773.92 1409.92,829.92 1334.92,829.92 1291.46,786.46 v1(1291.46,748.39)
VDD3V3: C27.2 C29.2 C30.2 C33.2 C34.2 C35.2 C36.2 C37.2 C39.2 C40.2 C41.2 C42.2 C45.2 D3.2 ICSP.2 L1.1 LS1.1 POWER.3 POWER.4 R15.1 R17.2 R18.2 R19.2 R22.2 R23.2 R24.2 R34.2 R43.2 S2.2 TP4.1 U1.37 U1.38 U2.3 U2.4 U2.13 U4.10 U4.17 U4.28 U4.40 U4.42 | length 5766.6
  Top Layer w9: C45.2 v1(1499.92,802.92) 1494.13,797.13 U2.4 1494.13,709.92 ccw(c1502.13,709.92) 1502.13,701.92 1505.82,701.92 ccw(c1505.82,709.92) 1513.82,709.92 U2.3
  Top Layer w10: C29.2 v1(1229.92,719.92) 1251.65,698.19 U2.13
  Top Layer w15: R43.2 1320.87,225.95 ; R19.2@1744.45,497.45 R15.1 1785.92,704.92 1837.92,756.92 1837.92,883.92 1773.92,947.92 TP4.1 1773.92,1114.92
  Top Layer w18: v1(226.92,534.92) R34.2 ; C36.2 v1(339.92,639.92) 357.8,622.05 U4.17 ; C27.2@384.92,962.36 C37.2 v1(439.92,934.92) 500,874.84 U4.10 ; C35.2@625.98,326.42 U4.28 ; U4.40 C33.2@920.98,653.54 ; U4.42 v1(889.92,716.54) C41.2@918.98,716.54 ; C41.2@920.39,721.89 R23.2 ; C41.2 C33.2 922.36,628.48 942.92,607.92 942.92,519.92 907.92,484.92 907.92,378.92 C34.2@946.07,340.77
  Top Layer w25: v1(794.92,922.92) R22.2 826.39,950.39 856.92,980.92 856.92,1013.92 957.92,1114.92 ; C40.2 931.92,326.62 C34.2@946.07,340.77
  Top Layer w30: ICSP.2 v1(320.08,870.08) 373.07,923.07 C27.2 ; D3.2@1004.92,269.66 v1@1004.92,303.66 ; C34.2@1004.92,352.92 v1@1004.92,303.66 ; 1384.92,228.83 L1.1 ; S2.2 1582.68,118.11 1472.87,227.92 1384.92,227.92 1168.76,227.92 LS1.1 v1@1004.92,303.66
  Bottom Layer w18: v1(226.92,534.92) 257.92,534.92 339.92,616.92 v1(339.92,639.92) 339.92,656.92 320.08,676.76 v1(320.08,870.08)
  Bottom Layer w25: v1(439.92,934.92) 603.92,934.92 615.92,922.92 v1(794.92,922.92) 794.92,811.54 v1(889.92,716.54) ; v1(625.92,359.92) 906.92,359.92 958.92,307.92 v1(1005.92,307.92) ; v1(1229.92,719.92) 1229.92,788.92 1306.92,865.92 1499.92,865.92 ; v1(1499.92,802.92) 1499.92,865.92 ; v1(1499.92,1113.92) 1499.92,865.92
VDD33_1: C9.2 C10.2 C11.2 C12.2 C13.2 L1.2 U2.9 U2.20 U2.30 U2.48 | length 1576.5
  Top Layer w8: C13.2 v1(1229.92,509.92) 1229.92,539.92 1250.39,560.39 U2.20 ; U2.9 v1(1395.71,794.92) 1395.71,808.15 C10.2 ; C11.2 U2.30 ; U2.48 1633.35,698.19 1645.98,710.83 v1(1645.98,745.98) 1659.92,759.92 C12.2@1682.36,759.92
  Top Layer w20: C9.2 L1.2 ; L1.2@1385.08,347.64 C11.2
  Bottom Layer w20: v1(1229.92,509.92) 1249.92,509.92 1374.92,384.92 v1(1434.92,384.92) 1434.92,614.92 1479.92,659.92 1599.92,659.92 1645.98,705.98 v1(1645.98,745.98) 1444.65,745.98 v1(1395.71,794.92)
WAN_LED1: R4.1 U1.8 | length 1557.3
  Top Layer w10: U1.8 2814.96,180.96 2972.92,338.92 v1(2972.92,447.92) ; v1(4011.92,678.92) R4.1
  Bottom Layer w10: v1(2972.92,447.92) 3203.92,678.92 v1(4011.92,678.92)
WAN_LED2: R33.1 U1.12 | length 1918.8
  Top Layer w10: U1.12 v2(3129.92,488.19) ; v2(4539.37,657.48) 4559.06,677.17 R33.1
  Bottom Layer w10: v2(3129.92,488.19) 3228.35,586.61 4468.5,586.61 v2(4539.37,657.48)
WAN_RX_N: R2.2 T1.8 U1.21 | length 1774.4
  Top Layer w8: U1.21 3602.37,1200.37 3634.74,1232.74 3634.74,1255.72 3667.94,1288.92 3720.72,1288.92 3773.92,1235.72 3773.92,540.72 3830.72,483.92 3994.92,483.92 ; R2.2@3994.92,514.92 3994.92,483.92 ; T1.8 4464.92,381.92 4420.92,425.92 4420.92,448.92 4385.92,483.92 3994.92,483.92
WAN_RX_P: R1.2 T1.6 U1.20 | length 1773.7
  Top Layer w8: U1.20 3681.11,1200.73 3648.74,1233.1 3648.74,1249.92 3673.74,1274.92 3714.92,1274.92 3759.92,1229.92 3759.92,1080.92 3759.92,1072.92 3759.92,1056.92 3751.92,1056.92 3751.92,1040.92 3759.92,1040.92 3759.92,1024.92 3751.92,1024.92 3751.92,1008.92 3759.92,1008.92 3759.92,992.92 3751.92,992.92 3751.92,976.92 3759.92,976.92 3759.92,960.92 3759.92,948.92 3759.92,534.92 3824.92,469.92 3994.92,469.92 ; R1.2@3994.92,440.39 3994.92,469.92 ; T1.6 4364.92,381.92 4406.92,423.92 4406.92,443.12 4380.12,469.92 3994.92,469.92
WAN_TX_N: R6.2 T1.3 U1.23 | length 1774.4
  Top Layer w8: U1.23 3444.89,1165.35 3476.92,1133.32 3476.92,880.92 3476.92,856.92 3453.05,856.92 3453.05,840.92 3476.92,840.92 3476.92,824.92 3453.05,824.92 3453.05,808.92 3476.92,808.92 3476.92,792.92 3453.05,792.92 3453.05,776.92 3476.92,776.92 3476.92,760.92 3453.05,760.92 3453.05,744.92 3476.92,744.92 3476.92,728.92 3453.05,728.92 3453.05,712.92 3476.92,712.92 3476.92,704.92 3476.92,663.12 3885.12,254.92 3934.92,254.92 ; R6.2@3934.92,225.39 3934.92,254.92 ; T1.3 4214.92,344.92 4171.92,301.92 4171.92,286.92 4139.92,254.92 3934.92,254.92
WAN_TX_P: R3.2 T1.1 U1.22 | length 1774.4
  Top Layer w8: U1.22 3523.63,1165.36 3490.92,1132.65 3490.92,1110.92 3490.92,1102.92 3514.61,1102.92 3514.61,1086.92 3490.92,1086.92 3490.92,1070.92 3514.61,1070.92 3514.61,1054.92 3490.92,1054.92 3490.92,1038.92 3514.61,1038.92 3514.61,1022.92 3490.92,1022.92 3490.92,1006.92 3514.61,1006.92 3514.61,990.92 3490.92,990.92 3490.92,974.92 3514.61,974.92 3514.61,958.92 3490.92,958.92 3490.92,942.92 3514.61,942.92 3514.61,926.92 3490.92,926.92 3490.92,903.92 3490.92,668.92 3890.92,268.92 ; 3891.39,268.92 4134.12,268.92 4157.92,292.72 4157.92,302.92 4114.92,345.92 T1.1 ; 3935.39,269.39 R3.2
WANRX_N: J1.6 T1.9 | length 545.5
  Top Layer w8: J1.6 4288.92,1029.08 4288.92,958.72 4309.32,938.32 4314.98,932.66 4331.86,949.54 4343.17,938.23 4326.29,921.35 4337.61,910.04 4354.48,926.92 4365.8,915.6 4348.92,898.72 4350.82,896.82 4421.92,825.72 4421.92,772.92 4464.92,729.92 T1.9
WANRX_P: J1.3 T1.11 | length 545.5
  Top Layer w8: J1.3 4210.08,1139.53 4210.08,1053.71 4233.23,1030.55 4259.29,1030.55 4274.92,1014.92 4274.92,952.92 4407.92,819.92 4407.92,772.92 4364.92,729.92 T1.11
WANTX_N: J1.2 T1.14 | length 545.5
  Top Layer w8: J1.2 4169.29,1025.35 4169.92,1024.72 4169.92,927.92 4169.92,919.92 4190.29,919.92 4190.29,903.92 4169.92,903.92 4169.92,887.92 4190.29,887.92 4190.29,871.92 4169.92,871.92 4169.92,855.92 4190.29,855.92 4190.29,839.92 4169.92,839.92 4169.92,823.92 4190.29,823.92 4190.29,807.92 4169.92,807.92 4169.92,795.92 4169.92,769.92 4216.97,722.87 4216.97,711.97 T1.14@4220.28,708.66
WANTX_P: J1.1 T1.16 | length 545.5
  Top Layer w8: T1.16 4114.92,729.92 4155.92,770.92 4155.92,926.92 4155.92,934.92 4134.12,934.92 4134.12,950.92 4155.92,950.92 4155.92,966.92 4134.12,966.92 4134.12,982.92 4155.92,982.92 4155.92,998.92 4155.92,1006.92 4155.92,1018.92 4129.13,1045.71 J1.1
WIFI_LED: LED.3 U1.15 WIFI.1 | length 2441.8
  Top Layer w10: U1.15 v1@3366.14,548.14 ; v1(4458.92,457.92) 4521.92,394.92 4521.92,249.92 4570.92,200.92 WIFI.1
  Bottom Layer w10: v1(3365.92,547.92) 4368.92,547.92 v1(4458.92,457.92) 4786.92,457.92 4897.18,568.18 LED.3
pads on no net: J1. LS1. M1.0 M2.0 M3.0 M4.0 M5.0 M6.0 T1.4 T1.5 T1.12 T1.13 U1.2 U1.4 U1.5 U1.6 U1.7 U1.9 U1.10 U1.11 U1.24 U1.25 U1.26 U1.27 U1.28 U1.29 U1.30 U1.31 U1.32 U1.33 U1.34 U1.35 U1.49 U4.11 U4.14 U4.15 U4.19 U4.20 U4.26 U4.32 U4.35

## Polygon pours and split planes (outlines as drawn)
GND on Top Layer "GND1" (solid, pour order 11): 0,0 0,1377.95 5078.74,1377.95 5078.74,0
VDD3V3 on Top Layer "GND1" (solid, pour order 7): 2369.92,1310.92 2369.92,1134.92 2139.92,1134.92 2084.92,1079.92 2084.92,1021.92 1884.92,1021.92 1884.92,1067.92 1862.92,1089.92 952.92,1089.92 932.92,1109.92 932.92,1139.92 1756.92,1139.92 1756.92,1232.92 1749.92,1239.92 1749.92,1289.92 1759.92,1299.92 1889.92,1299.92 1894.92,1294.92 1894.92,1241.92 1885.92,1232.92 1885.92,1155.92 1907.92,1133.92 2044.92,1133.92 2129.92,1218.92 2221.92,1310.92 2369.92,1310.92
GND on Bottom Layer "GND1" (solid, pour order 9): 0,1377.95 5078.74,1377.95 5078.74,0 0,0

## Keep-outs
Keep-Out Layer:
  the board outline again, w8

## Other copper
Top Layer:
  rectangle net NetC4_2: 4647.92,375.92 4705.92,632.92
  rectangle net VDD3V3: 970.92,232.92 1036.92,371.92
  rectangle net VDD3V3: 912.92,262.92 970.92,371.92
  pour cut-out: 3904.92,1377.95 3904.92,554.92 4629.92,554.92 4629.92,1377.95
Bottom Layer:
  pour cut-out: 3904.92,1377.95 3904.92,554.92 4629.92,554.92 4629.92,1377.95

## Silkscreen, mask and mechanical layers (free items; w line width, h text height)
Top Overlay:
  circle w6: c4452.02,175.92 r2.24
  circle w6: c4425.26,177.92 r2.24
  lines w6: 4279.26,75.92 4294.26,107.92 4309.26,75.92 ; 4283.48,84.92 4305.04,84.92 ; 4321.26,76.92 4321.26,107.92 4347.26,76.92 4347.26,107.92 ; 4360.26,107.92 4381.26,107.92 ; 4371.26,75.92 4371.26,107.92 ; 4416.26,124.92 4431.26,124.92 ; 4420.26,102.92 4409.26,86.92 4396.26,105.92 4396.26,76.92 4394.26,76.92 4394.26,105.92 4399.26,105.92 4408.26,88.92 4420.26,105.92 4424.26,105.92 4424.26,76.92 4422.26,76.92 4422.26,105.92 ; 4420.26,129.92 4444.26,130.92 4428.26,132.92 ; 4421.47,135.84 cw(c4468.26,153.92) 4422.26,173.92 ; 4432.73,140.59 cw(c4471.26,142.92) 4450.54,175.49 ; 4456.26,105.92 4479.26,76.92 ; 4458.26,105.92 4458.26,76.92 4455.26,76.92 4455.26,105.92 4459.26,105.92 4478.26,81.92 ; 4495.26,77.92 4517.26,77.92 4517.26,76.92 4495.26,76.92 4495.26,105.92 4517.26,105.92 ; 4498.26,77.92 4498.26,105.92 ; 4498.26,91.92 4516.26,91.92 ; 4531.26,87.92 4546.11,87.92 ; 4531.26,88.92 4547.11,88.92 ccw(c4547.11,89.24) 4547.43,89.24 ; 4541.26,87.92 4550.26,76.92 4554.26,76.92 4546.11,85.07 4546.11,87.92 ; 4479.26,76.92 4479.26,105.92 4481.26,105.92 4481.26,76.92 4479.26,76.92 ; 4529.26,105.92 cw(c4529.26,103.92) 4531.26,103.92 4531.26,76.92 4529.26,76.92 4529.26,105.92 ; 4529.26,105.92 4549.26,105.92 cw(c4545.26,97.92) 4547.43,89.24 ; 4546.11,87.92 ccw(c4546.11,89.24) 4547.43,89.24 ; 4413.42,119.89 cw(c4434.26,115.92) 4455.26,118.92 4451.23,119.24 ccw(c4440.26,117.92) 4429.39,119.9 4413.42,119.89 ; 4438.26,76.92 4441.26,76.92 4441.26,105.92 4438.26,105.92 4438.26,76.92
  text "Bitmaintech V1.2 2013/11/29" at 2688.98,1283.46 h40

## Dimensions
0,1377.95 to 0,0 on Mechanical 1
0,1377.95 to 5078.74,1377.95 on Mechanical 1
